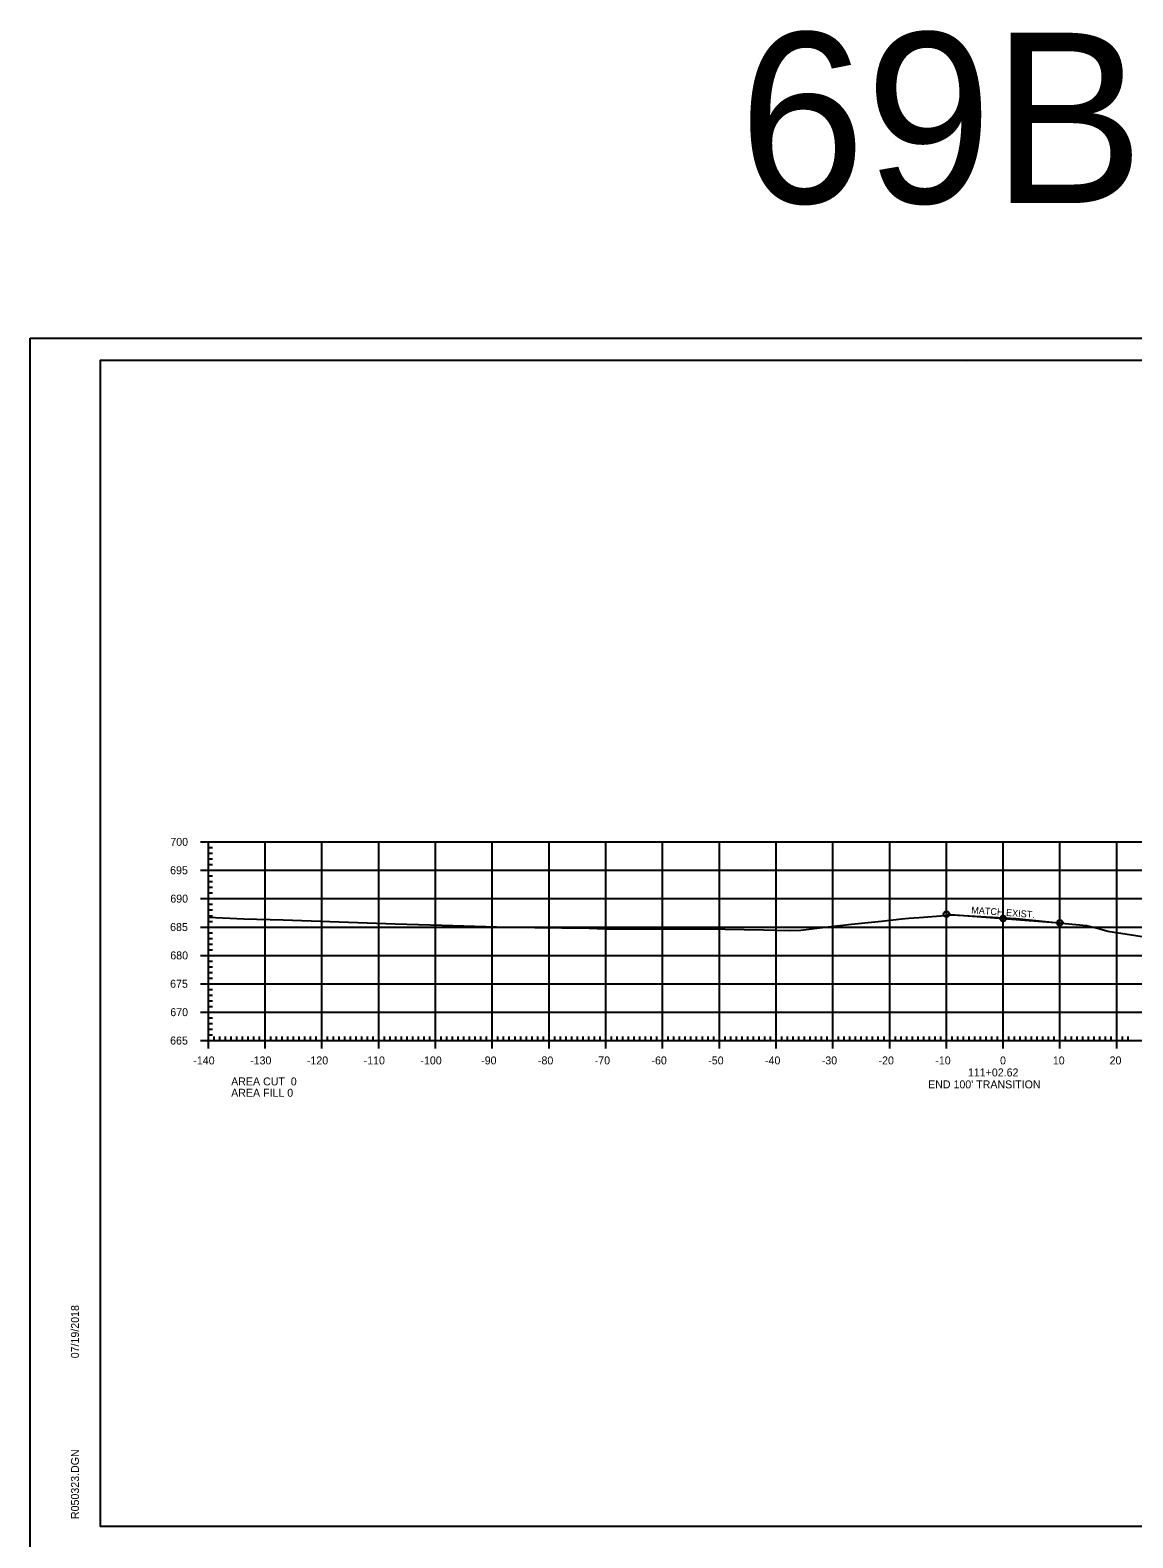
# Model space of a CAD drawing. Extents: x 1360146 to 1361431, y 631444 to 632352.
# Drawn here: x 1360146.4 to 1360340.6, y 632086.2 to 632351.8 of the extents above; entities that cross this region are included whole.
import ezdxf

# ---------------------------------------------------------------- set-up
doc = ezdxf.new("R2010")
doc.units = 0
for name, color, linetype in [('Default', 7, 'Continuous'), ('R_Axis', 7, 'Continuous'), ('R_Axis Annot', 7, 'Continuous'), ('R_Border', 7, 'Continuous'), ('R_Exist Surface', 7, 'Continuous'), ('R_Fin Surface', 7, 'Continuous'), ('R_Fin Surface Annot', 7, 'Continuous'), ('R_Grid', 7, 'Continuous'), ('R_No Plot', 7, 'Continuous')]:
    doc.layers.add(name, color=color, linetype=linetype)

msp = doc.modelspace()

# ---------------------------------------------------------------- linework, layer by layer
at = {"layer": 'R_Axis'}
for p, q in [((1360176.37, 632208.77), (1360177.77, 632208.77)), ((1360177.77, 632173.77), (1360177.77, 632208.77)), ((1360177.77, 632207.77), (1360178.47, 632207.77)), ((1360177.77, 632206.77), (1360178.47, 632206.77)), ((1360176.37, 632203.77), (1360177.77, 632203.77)), ((1360177.77, 632205.77), (1360178.47, 632205.77)), ((1360177.77, 632204.77), (1360178.47, 632204.77)), ((1360177.77, 632202.77), (1360178.47, 632202.77)), ((1360177.77, 632201.77), (1360178.47, 632201.77)), ((1360176.37, 632198.77), (1360177.77, 632198.77)), ((1360177.77, 632200.77), (1360178.47, 632200.77)), ((1360177.77, 632199.77), (1360178.47, 632199.77)), ((1360177.77, 632197.77), (1360178.47, 632197.77)), ((1360177.77, 632196.77), (1360178.47, 632196.77)), ((1360177.77, 632195.77), (1360178.47, 632195.77)), ((1360176.37, 632193.77), (1360177.77, 632193.77)), ((1360177.77, 632194.77), (1360178.47, 632194.77)), ((1360177.77, 632192.77), (1360178.47, 632192.77)), ((1360177.77, 632191.77), (1360178.47, 632191.77)), ((1360177.77, 632190.77), (1360178.47, 632190.77)), ((1360176.37, 632188.77), (1360177.77, 632188.77)), ((1360177.77, 632189.77), (1360178.47, 632189.77)), ((1360177.77, 632187.77), (1360178.47, 632187.77)), ((1360177.77, 632186.77), (1360178.47, 632186.77)), ((1360177.77, 632185.77), (1360178.47, 632185.77)), ((1360176.37, 632183.77), (1360177.77, 632183.77)), ((1360177.77, 632184.77), (1360178.47, 632184.77)), ((1360177.77, 632182.77), (1360178.47, 632182.77)), ((1360177.77, 632181.77), (1360178.47, 632181.77)), ((1360177.77, 632180.77), (1360178.47, 632180.77)), ((1360177.77, 632179.77), (1360178.47, 632179.77)), ((1360176.37, 632178.77), (1360177.77, 632178.77)), ((1360177.77, 632177.77), (1360178.47, 632177.77)), ((1360177.77, 632176.77), (1360178.47, 632176.77)), ((1360177.77, 632175.77), (1360178.47, 632175.77)), ((1360177.77, 632174.77), (1360178.47, 632174.77)), ((1360178.77, 632173.77), (1360178.77, 632174.47)), ((1360179.77, 632173.77), (1360179.77, 632174.47)), ((1360180.77, 632173.77), (1360180.77, 632174.47)), ((1360181.77, 632173.77), (1360181.77, 632174.47)), ((1360182.77, 632173.77), (1360182.77, 632174.47)), ((1360183.77, 632173.77), (1360183.77, 632174.47)), ((1360184.77, 632173.77), (1360184.77, 632174.47)), ((1360185.77, 632173.77), (1360185.77, 632174.47)), ((1360186.77, 632173.77), (1360186.77, 632174.47)), ((1360188.77, 632173.77), (1360188.77, 632174.47)), ((1360189.77, 632173.77), (1360189.77, 632174.47)), ((1360190.77, 632173.77), (1360190.77, 632174.47)), ((1360191.77, 632173.77), (1360191.77, 632174.47)), ((1360192.77, 632173.77), (1360192.77, 632174.47)), ((1360193.77, 632173.77), (1360193.77, 632174.47)), ((1360194.77, 632173.77), (1360194.77, 632174.47)), ((1360195.77, 632173.77), (1360195.77, 632174.47)), ((1360196.77, 632173.77), (1360196.77, 632174.47)), ((1360198.77, 632173.77), (1360198.77, 632174.47)), ((1360199.77, 632173.77), (1360199.77, 632174.47)), ((1360200.77, 632173.77), (1360200.77, 632174.47)), ((1360201.77, 632173.77), (1360201.77, 632174.47)), ((1360202.77, 632173.77), (1360202.77, 632174.47)), ((1360203.77, 632173.77), (1360203.77, 632174.47)), ((1360204.77, 632173.77), (1360204.77, 632174.47)), ((1360205.77, 632173.77), (1360205.77, 632174.47)), ((1360206.77, 632173.77), (1360206.77, 632174.47)), ((1360208.77, 632173.77), (1360208.77, 632174.47)), ((1360209.77, 632173.77), (1360209.77, 632174.47)), ((1360210.77, 632173.77), (1360210.77, 632174.47)), ((1360211.77, 632173.77), (1360211.77, 632174.47)), ((1360212.77, 632173.77), (1360212.77, 632174.47)), ((1360213.77, 632173.77), (1360213.77, 632174.47)), ((1360214.77, 632173.77), (1360214.77, 632174.47)), ((1360215.77, 632173.77), (1360215.77, 632174.47)), ((1360216.77, 632173.77), (1360216.77, 632174.47)), ((1360218.77, 632173.77), (1360218.77, 632174.47)), ((1360219.77, 632173.77), (1360219.77, 632174.47)), ((1360220.77, 632173.77), (1360220.77, 632174.47)), ((1360221.77, 632173.77), (1360221.77, 632174.47)), ((1360222.77, 632173.77), (1360222.77, 632174.47)), ((1360223.77, 632173.77), (1360223.77, 632174.47)), ((1360224.77, 632173.77), (1360224.77, 632174.47)), ((1360225.77, 632173.77), (1360225.77, 632174.47)), ((1360226.77, 632173.77), (1360226.77, 632174.47)), ((1360228.77, 632173.77), (1360228.77, 632174.47)), ((1360229.77, 632173.77), (1360229.77, 632174.47)), ((1360230.77, 632173.77), (1360230.77, 632174.47)), ((1360231.77, 632173.77), (1360231.77, 632174.47)), ((1360232.77, 632173.77), (1360232.77, 632174.47)), ((1360233.77, 632173.77), (1360233.77, 632174.47)), ((1360234.77, 632173.77), (1360234.77, 632174.47)), ((1360235.77, 632173.77), (1360235.77, 632174.47)), ((1360236.77, 632173.77), (1360236.77, 632174.47)), ((1360238.77, 632173.77), (1360238.77, 632174.47)), ((1360239.77, 632173.77), (1360239.77, 632174.47)), ((1360240.77, 632173.77), (1360240.77, 632174.47)), ((1360241.77, 632173.77), (1360241.77, 632174.47)), ((1360242.77, 632173.77), (1360242.77, 632174.47)), ((1360243.77, 632173.77), (1360243.77, 632174.47)), ((1360244.77, 632173.77), (1360244.77, 632174.47)), ((1360245.77, 632173.77), (1360245.77, 632174.47)), ((1360246.77, 632173.77), (1360246.77, 632174.47)), ((1360248.77, 632173.77), (1360248.77, 632174.47)), ((1360249.77, 632173.77), (1360249.77, 632174.47)), ((1360250.77, 632173.77), (1360250.77, 632174.47)), ((1360251.77, 632173.77), (1360251.77, 632174.47)), ((1360252.77, 632173.77), (1360252.77, 632174.47)), ((1360253.77, 632173.77), (1360253.77, 632174.47)), ((1360254.77, 632173.77), (1360254.77, 632174.47)), ((1360255.77, 632173.77), (1360255.77, 632174.47)), ((1360256.77, 632173.77), (1360256.77, 632174.47)), ((1360258.77, 632173.77), (1360258.77, 632174.47)), ((1360259.77, 632173.77), (1360259.77, 632174.47)), ((1360260.77, 632173.77), (1360260.77, 632174.47)), ((1360261.77, 632173.77), (1360261.77, 632174.47)), ((1360262.77, 632173.77), (1360262.77, 632174.47)), ((1360263.77, 632173.77), (1360263.77, 632174.47)), ((1360264.77, 632173.77), (1360264.77, 632174.47)), ((1360265.77, 632173.77), (1360265.77, 632174.47)), ((1360266.77, 632173.77), (1360266.77, 632174.47)), ((1360268.77, 632173.77), (1360268.77, 632174.47)), ((1360269.77, 632173.77), (1360269.77, 632174.47)), ((1360270.77, 632173.77), (1360270.77, 632174.47)), ((1360271.77, 632173.77), (1360271.77, 632174.47)), ((1360272.77, 632173.77), (1360272.77, 632174.47)), ((1360273.77, 632173.77), (1360273.77, 632174.47)), ((1360274.77, 632173.77), (1360274.77, 632174.47)), ((1360275.77, 632173.77), (1360275.77, 632174.47)), ((1360276.77, 632173.77), (1360276.77, 632174.47)), ((1360278.77, 632173.77), (1360278.77, 632174.47)), ((1360279.77, 632173.77), (1360279.77, 632174.47)), ((1360280.77, 632173.77), (1360280.77, 632174.47)), ((1360281.77, 632173.77), (1360281.77, 632174.47)), ((1360282.77, 632173.77), (1360282.77, 632174.47)), ((1360283.77, 632173.77), (1360283.77, 632174.47)), ((1360284.77, 632173.77), (1360284.77, 632174.47)), ((1360285.77, 632173.77), (1360285.77, 632174.47)), ((1360286.77, 632173.77), (1360286.77, 632174.47)), ((1360288.77, 632173.77), (1360288.77, 632174.47)), ((1360289.77, 632173.77), (1360289.77, 632174.47)), ((1360290.77, 632173.77), (1360290.77, 632174.47)), ((1360291.77, 632173.77), (1360291.77, 632174.47)), ((1360292.77, 632173.77), (1360292.77, 632174.47)), ((1360293.77, 632173.77), (1360293.77, 632174.47)), ((1360294.77, 632173.77), (1360294.77, 632174.47)), ((1360295.77, 632173.77), (1360295.77, 632174.47)), ((1360296.77, 632173.77), (1360296.77, 632174.47)), ((1360298.77, 632173.77), (1360298.77, 632174.47)), ((1360299.77, 632173.77), (1360299.77, 632174.47)), ((1360300.77, 632173.77), (1360300.77, 632174.47)), ((1360301.77, 632173.77), (1360301.77, 632174.47)), ((1360302.77, 632173.77), (1360302.77, 632174.47)), ((1360303.77, 632173.77), (1360303.77, 632174.47)), ((1360304.77, 632173.77), (1360304.77, 632174.47)), ((1360305.77, 632173.77), (1360305.77, 632174.47)), ((1360306.77, 632173.77), (1360306.77, 632174.47)), ((1360308.77, 632173.77), (1360308.77, 632174.47)), ((1360309.77, 632173.77), (1360309.77, 632174.47)), ((1360310.77, 632173.77), (1360310.77, 632174.47)), ((1360311.77, 632173.77), (1360311.77, 632174.47)), ((1360312.77, 632173.77), (1360312.77, 632174.47)), ((1360313.77, 632173.77), (1360313.77, 632174.47)), ((1360314.77, 632173.77), (1360314.77, 632174.47)), ((1360315.77, 632173.77), (1360315.77, 632174.47)), ((1360316.77, 632173.77), (1360316.77, 632174.47)), ((1360318.77, 632173.77), (1360318.77, 632174.47)), ((1360319.77, 632173.77), (1360319.77, 632174.47)), ((1360320.77, 632173.77), (1360320.77, 632174.47)), ((1360321.77, 632173.77), (1360321.77, 632174.47)), ((1360322.77, 632173.77), (1360322.77, 632174.47)), ((1360323.77, 632173.77), (1360323.77, 632174.47)), ((1360324.77, 632173.77), (1360324.77, 632174.47)), ((1360325.77, 632173.77), (1360325.77, 632174.47)), ((1360326.77, 632173.77), (1360326.77, 632174.47)), ((1360328.77, 632173.77), (1360328.77, 632174.47)), ((1360329.77, 632173.77), (1360329.77, 632174.47)), ((1360330.77, 632173.77), (1360330.77, 632174.47)), ((1360331.77, 632173.77), (1360331.77, 632174.47)), ((1360332.77, 632173.77), (1360332.77, 632174.47)), ((1360333.77, 632173.77), (1360333.77, 632174.47)), ((1360334.77, 632173.77), (1360334.77, 632174.47)), ((1360335.77, 632173.77), (1360335.77, 632174.47)), ((1360336.77, 632173.77), (1360336.77, 632174.47)), ((1360338.77, 632173.77), (1360338.77, 632174.47)), ((1360339.77, 632173.77), (1360339.77, 632174.47)), ((1360176.37, 632173.77), (1360177.77, 632173.77)), ((1360177.77, 632173.77), (1360457.77, 632173.77)), ((1360177.77, 632172.37), (1360177.77, 632173.77)), ((1360187.77, 632172.37), (1360187.77, 632173.77)), ((1360197.77, 632172.37), (1360197.77, 632173.77)), ((1360207.77, 632172.37), (1360207.77, 632173.77)), ((1360217.77, 632172.37), (1360217.77, 632173.77)), ((1360227.77, 632172.37), (1360227.77, 632173.77)), ((1360237.77, 632172.37), (1360237.77, 632173.77)), ((1360247.77, 632172.37), (1360247.77, 632173.77)), ((1360257.77, 632172.37), (1360257.77, 632173.77)), ((1360267.77, 632172.37), (1360267.77, 632173.77)), ((1360277.77, 632172.37), (1360277.77, 632173.77)), ((1360287.77, 632172.37), (1360287.77, 632173.77)), ((1360297.77, 632172.37), (1360297.77, 632173.77)), ((1360307.77, 632172.37), (1360307.77, 632173.77)), ((1360317.77, 632172.37), (1360317.77, 632173.77)), ((1360327.77, 632172.37), (1360327.77, 632173.77)), ((1360337.77, 632172.37), (1360337.77, 632173.77))]:
    msp.add_line(p, q, dxfattribs=at)
at = {"layer": 'R_Border'}
for p, q in [((1360158.77, 632293.62), (1360474.95, 632293.62)), ((1360158.77, 632088.16), (1360158.77, 632293.62)), ((1360311.29, 632293.36), (1360311.29, 632293.36)), ((1360311.29, 632293.36), (1360311.29, 632293.36)), ((1360158.77, 632088.16), (1360158.77, 632088.16)), ((1360474.95, 632088.16), (1360158.77, 632088.16))]:
    msp.add_line(p, q, dxfattribs=at)
at = {"layer": 'R_Exist Surface'}
msp.add_lwpolyline([(1360177.77, 632195.53), (1360183.99, 632195.21), (1360190.93, 632195.02), (1360210.68, 632194.31), (1360218.9, 632194.12), (1360230.45, 632193.77), (1360244.81, 632193.58), (1360247.58, 632193.46), (1360252.21, 632193.48), (1360265.41, 632193.43), (1360275.52, 632193.26), (1360280.07, 632193.16), (1360282.11, 632193.23), (1360285.39, 632193.6), (1360291.06, 632194.27), (1360296.3, 632194.83), (1360299.93, 632195.22), (1360301.12, 632195.32), (1360302.94, 632195.44), (1360306, 632195.7), (1360308.8, 632195.92), (1360314.84, 632195.57), (1360320.05, 632195.27), (1360328.67, 632194.42), (1360332.43, 632194.05), (1360334.79, 632193.44), (1360336.22, 632193.04), (1360346.04, 632191.5)], dxfattribs=at)
at = {"layer": 'R_Fin Surface'}
msp.add_lwpolyline([(1360307.77, 632196.03), (1360317.77, 632195.27), (1360327.77, 632194.51)], dxfattribs=at)
at = {"layer": 'R_Grid'}
for p, q in [((1360177.77, 632208.77), (1360457.77, 632208.77)), ((1360177.77, 632173.77), (1360177.77, 632208.77)), ((1360187.77, 632173.77), (1360187.77, 632208.77)), ((1360197.77, 632173.77), (1360197.77, 632208.77)), ((1360207.77, 632173.77), (1360207.77, 632208.77)), ((1360217.77, 632173.77), (1360217.77, 632208.77)), ((1360227.77, 632173.77), (1360227.77, 632208.77)), ((1360237.77, 632173.77), (1360237.77, 632208.77)), ((1360247.77, 632173.77), (1360247.77, 632208.77)), ((1360257.77, 632173.77), (1360257.77, 632208.77)), ((1360267.77, 632173.77), (1360267.77, 632208.77)), ((1360277.77, 632173.77), (1360277.77, 632208.77)), ((1360287.77, 632173.77), (1360287.77, 632208.77)), ((1360297.77, 632173.77), (1360297.77, 632208.77)), ((1360307.77, 632173.77), (1360307.77, 632208.77)), ((1360317.77, 632173.77), (1360317.77, 632208.77)), ((1360327.77, 632173.77), (1360327.77, 632208.77)), ((1360337.77, 632173.77), (1360337.77, 632208.77)), ((1360177.77, 632203.77), (1360457.77, 632203.77)), ((1360177.77, 632198.77), (1360457.77, 632198.77)), ((1360177.77, 632193.77), (1360457.77, 632193.77)), ((1360177.77, 632188.77), (1360457.77, 632188.77)), ((1360177.77, 632183.77), (1360457.77, 632183.77)), ((1360177.77, 632178.77), (1360457.77, 632178.77)), ((1360177.77, 632173.77), (1360457.77, 632173.77))]:
    msp.add_line(p, q, dxfattribs=at)
at = {"layer": 'R_No Plot'}
msp.add_line((1360146.37, 632297.51), (1360479.7, 632297.51), dxfattribs=at)
for points in [[(1360146.36, 632297.51), (1360479.7, 632297.51), (1360479.7, 632084.17), (1360146.36, 632084.17)], [(1360392.69, 632293.62), (1360392.69, 632283.74), (1360428.42, 632283.74), (1360428.42, 632280.82), (1360451.62, 632280.82), (1360451.62, 632256.49), (1360474.95, 632256.49), (1360474.95, 632088.16), (1360158.77, 632088.16), (1360158.77, 632293.62)]]:
    msp.add_lwpolyline(points, close=True, dxfattribs=at)
for centre in [(1360307.77, 632196.03), (1360317.77, 632195.27), (1360327.77, 632194.51)]:
    msp.add_circle(centre, 0.5, dxfattribs=at)

# ---------------------------------------------------------------- texts
at = {"layer": 'Default'}
msp.add_text('69B', height=30, dxfattribs=at).set_placement((1360271.17, 632321.31))
at = {"layer": 'R_Axis Annot'}
for s, p in [('700', (1360171.05, 632208.07)), ('695', (1360171.02, 632203.07)), ('690', (1360171.05, 632198.07)), ('685', (1360171.02, 632193.07)), ('680', (1360171.05, 632188.07)), ('675', (1360171.02, 632183.07)), ('670', (1360171.05, 632178.07)), ('665', (1360171.02, 632173.07)), ('-140', (1360175.11, 632169.57)), ('-130', (1360185.11, 632169.57)), ('-120', (1360195.11, 632169.57)), ('-110', (1360205.11, 632169.57)), ('-100', (1360215.11, 632169.57)), ('-90', (1360225.81, 632169.57)), ('-80', (1360235.81, 632169.57)), ('-70', (1360245.81, 632169.57)), ('-60', (1360255.81, 632169.57)), ('-50', (1360265.81, 632169.57)), ('-40', (1360275.81, 632169.57)), ('-30', (1360285.81, 632169.57)), ('-20', (1360295.81, 632169.57)), ('-10', (1360305.81, 632169.57)), ('0', (1360317.21, 632169.57)), ('10', (1360326.51, 632169.57)), ('20', (1360336.51, 632169.57)), ('AREA CUT  0', (1360181.77, 632165.87)), ("END 100' TRANSITION", (1360304.54, 632165.35)), ('111+02.62', (1360311.55, 632167.45)), ('AREA FILL 0', (1360181.77, 632163.87))]:
    msp.add_text(s, height=1.4, dxfattribs=at).set_placement(p)
at = {"layer": 'R_Border'}
for s, p in [('07/19/2018', (1360154.96, 632117.8)), ('R050323.DGN', (1360154.96, 632089.48))]:
    msp.add_text(s, height=1.4, rotation=90, dxfattribs=at).set_placement(p)
at = {"layer": 'R_Fin Surface Annot'}
msp.add_text('MATCH EXIST.', height=1.2, rotation=355.6497, dxfattribs=at).set_placement((1360312.1, 632196.2))

doc.saveas('drawing.dxf')
